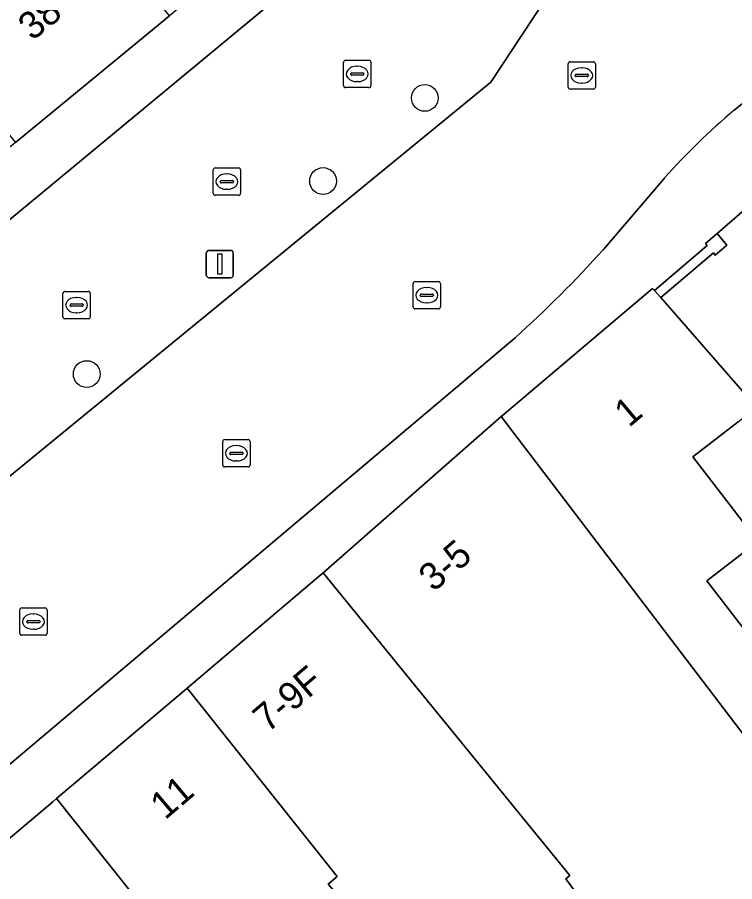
# Model space of a CAD drawing. Extents: x 161087 to 161926, y 382572 to 383873.
# Drawn here: x 161336.63 to 161362.85, y 383067.62 to 383099.2 of the extents above; entities that cross this region are included whole.
import ezdxf

# ---------------------------------------------------------------- set-up
doc = ezdxf.new("R2010")
doc.units = 0
for name, color, linetype in [('IMGEO_Boom', 7, 'Continuous'), ('IMGEO_Erf', 7, 'Continuous'), ('IMGEO_Kolk', 7, 'Continuous'), ('IMGEO_Lichtmast', 7, 'Continuous'), ('IMGEO_Muur', 7, 'Continuous'), ('IMGEO_Pand', 7, 'Continuous'), ('IMGEO_Pand_nummerreeks', 7, 'Continuous'), ('IMGEO_Rijbaan_lokaal_open', 7, 'Continuous'), ('IMGEO_Voetgangersgebied_open', 7, 'Continuous'), ('IMGEO_Voetpad_open', 7, 'Continuous')]:
    doc.layers.add(name, color=color, linetype=linetype)

msp = doc.modelspace()

# ---------------------------------------------------------------- linework, layer by layer
at = {"layer": 'IMGEO_Boom'}
for centre in [(161351.524, 383096.259), (161347.806, 383093.222), (161339.171, 383086.168)]:
    msp.add_circle(centre, 0.489, dxfattribs=at)
at = {"layer": 'IMGEO_Erf'}
for points in [[(161363.584, 383092.504), (161362.202, 383091.306), (161362.565, 383090.88), (161362.138, 383090.517), (161362.067, 383090.601), (161360.142, 383088.963), (161363.648, 383084.959)], [(161362.972, 383084.424), (161361.312, 383083.146), (161362.666, 383081.388), (161363.693, 383080.054), (161361.831, 383078.62), (161365.218, 383074.222)]]:
    msp.add_lwpolyline(points, dxfattribs=at)
at = {"layer": 'IMGEO_Kolk'}
for p, q in [((161348.631, 383097.633), (161349.483, 383097.633)), ((161348.556, 383096.707), (161348.556, 383097.559)), ((161349.044, 383097.413), (161349.069, 383097.413)), ((161349.557, 383097.559), (161349.557, 383096.707)), ((161356.758, 383096.653), (161356.758, 383097.505)), ((161356.833, 383097.579), (161357.685, 383097.579)), ((161357.246, 383097.359), (161357.271, 383097.359)), ((161357.759, 383097.505), (161357.759, 383096.653)), ((161348.815, 383097.127), (161348.815, 383097.139)), ((161349.253, 383097.09), (161348.855, 383097.09)), ((161348.858, 383097.176), (161349.256, 383097.176)), ((161349.299, 383097.139), (161349.299, 383097.127)), ((161357.017, 383097.073), (161357.017, 383097.085)), ((161357.455, 383097.036), (161357.057, 383097.036)), ((161357.06, 383097.122), (161357.458, 383097.122)), ((161357.501, 383097.085), (161357.501, 383097.073)), ((161349.067, 383096.853), (161349.042, 383096.853)), ((161357.269, 383096.799), (161357.244, 383096.799)), ((161349.483, 383096.633), (161348.631, 383096.633)), ((161357.685, 383096.579), (161356.833, 383096.579)), ((161343.792, 383092.773), (161343.792, 383093.625)), ((161343.867, 383093.699), (161344.719, 383093.699)), ((161344.793, 383093.625), (161344.793, 383092.773)), ((161344.051, 383093.193), (161344.051, 383093.205)), ((161344.094, 383093.242), (161344.492, 383093.242)), ((161344.28, 383093.479), (161344.305, 383093.479)), ((161344.535, 383093.205), (161344.535, 383093.193)), ((161344.489, 383093.156), (161344.091, 383093.156)), ((161344.303, 383092.919), (161344.278, 383092.919)), ((161344.719, 383092.699), (161343.867, 383092.699)), ((161351.096, 383088.623), (161351.096, 383089.475)), ((161351.171, 383089.549), (161352.023, 383089.549)), ((161352.097, 383089.475), (161352.097, 383088.623)), ((161338.301, 383088.263), (161338.301, 383089.115)), ((161338.376, 383089.189), (161339.228, 383089.189)), ((161339.302, 383089.115), (161339.302, 383088.263)), ((161351.584, 383089.329), (161351.609, 383089.329)), ((161338.789, 383088.969), (161338.814, 383088.969)), ((161351.355, 383089.043), (161351.355, 383089.055)), ((161351.793, 383089.006), (161351.395, 383089.006)), ((161351.398, 383089.092), (161351.796, 383089.092)), ((161351.839, 383089.055), (161351.839, 383089.043)), ((161338.56, 383088.683), (161338.56, 383088.695)), ((161338.998, 383088.646), (161338.6, 383088.646)), ((161338.603, 383088.732), (161339.001, 383088.732)), ((161339.044, 383088.695), (161339.044, 383088.683)), ((161352.023, 383088.549), (161351.171, 383088.549)), ((161351.607, 383088.769), (161351.582, 383088.769)), ((161339.228, 383088.189), (161338.376, 383088.189)), ((161338.812, 383088.409), (161338.787, 383088.409)), ((161344.214, 383083.774), (161345.066, 383083.774)), ((161344.139, 383082.848), (161344.139, 383083.7)), ((161344.627, 383083.554), (161344.652, 383083.554)), ((161345.14, 383083.7), (161345.14, 383082.848)), ((161344.398, 383083.268), (161344.398, 383083.28)), ((161344.836, 383083.231), (161344.438, 383083.231)), ((161344.441, 383083.317), (161344.839, 383083.317)), ((161344.882, 383083.28), (161344.882, 383083.268)), ((161344.65, 383082.994), (161344.625, 383082.994)), ((161345.066, 383082.774), (161344.214, 383082.774)), ((161336.722, 383076.698), (161336.722, 383077.55)), ((161336.797, 383077.624), (161337.649, 383077.624)), ((161337.723, 383077.55), (161337.723, 383076.698)), ((161336.981, 383077.118), (161336.981, 383077.13)), ((161337.024, 383077.167), (161337.422, 383077.167)), ((161337.21, 383077.404), (161337.235, 383077.404)), ((161337.465, 383077.13), (161337.465, 383077.118)), ((161337.419, 383077.081), (161337.021, 383077.081)), ((161337.233, 383076.844), (161337.208, 383076.844)), ((161337.649, 383076.624), (161336.797, 383076.624))]:
    msp.add_line(p, q, dxfattribs=at)
for points in [[(161348.631, 383097.633), (161349.483, 383097.633)], [(161348.556, 383096.707), (161348.556, 383097.559)], [(161349.557, 383097.559), (161349.557, 383096.707)], [(161356.758, 383096.653), (161356.758, 383097.505)], [(161356.833, 383097.579), (161357.685, 383097.579)], [(161357.759, 383097.505), (161357.759, 383096.653)], [(161349.483, 383096.633), (161348.631, 383096.633)], [(161357.685, 383096.579), (161356.833, 383096.579)], [(161343.792, 383092.773), (161343.792, 383093.625)], [(161343.867, 383093.699), (161344.719, 383093.699)], [(161344.793, 383093.625), (161344.793, 383092.773)], [(161344.719, 383092.699), (161343.867, 383092.699)], [(161351.096, 383088.623), (161351.096, 383089.475)], [(161351.171, 383089.549), (161352.023, 383089.549)], [(161352.097, 383089.475), (161352.097, 383088.623)], [(161338.301, 383088.263), (161338.301, 383089.115)], [(161338.376, 383089.189), (161339.228, 383089.189)], [(161339.302, 383089.115), (161339.302, 383088.263)], [(161352.023, 383088.549), (161351.171, 383088.549)], [(161339.228, 383088.189), (161338.376, 383088.189)], [(161344.214, 383083.774), (161345.066, 383083.774)], [(161344.139, 383082.848), (161344.139, 383083.7)], [(161345.14, 383083.7), (161345.14, 383082.848)], [(161345.066, 383082.774), (161344.214, 383082.774)], [(161336.722, 383076.698), (161336.722, 383077.55)], [(161336.797, 383077.624), (161337.649, 383077.624)], [(161337.723, 383077.55), (161337.723, 383076.698)], [(161337.649, 383076.624), (161336.797, 383076.624)]]:
    msp.add_lwpolyline(points, dxfattribs=at)
for centre, radius, start, end in [((161348.633, 383097.557), 0.0765, 91.552, 178.448), ((161348.633, 383097.557), 0.0765, 91.552, 178.448), ((161349.481, 383097.557), 0.0765, 1.552, 88.448), ((161349.481, 383097.557), 0.0765, 1.552, 88.448), ((161356.835, 383097.503), 0.0765, 91.552, 178.448), ((161356.835, 383097.503), 0.0765, 91.552, 178.448), ((161357.683, 383097.503), 0.0765, 1.552, 88.448), ((161357.683, 383097.503), 0.0765, 1.552, 88.448), ((161348.855, 383097.136), 0.0403, 85.8775, 175.7526), ((161348.852, 383097.126), 0.0366, 178.938, 274.7102), ((161349.256, 383097.133), 0.043, 264.8664, 352.4533), ((161349.26, 383097.138), 0.0386, 1.7309, 96.639), ((161357.057, 383097.082), 0.0403, 85.8775, 175.7526), ((161357.054, 383097.072), 0.0366, 178.938, 274.7102), ((161357.458, 383097.079), 0.043, 264.8664, 352.4533), ((161357.462, 383097.084), 0.0386, 1.7309, 96.639), ((161348.633, 383096.709), 0.0765, 181.552, 268.448), ((161348.633, 383096.709), 0.0765, 181.552, 268.448), ((161349.481, 383096.709), 0.0765, 271.552, 358.448), ((161349.481, 383096.709), 0.0765, 271.552, 358.448), ((161356.835, 383096.655), 0.0765, 181.552, 268.448), ((161356.835, 383096.655), 0.0765, 181.552, 268.448), ((161357.683, 383096.655), 0.0765, 271.552, 358.448), ((161357.683, 383096.655), 0.0765, 271.552, 358.448), ((161343.869, 383093.623), 0.0765, 91.552, 178.448), ((161343.869, 383093.623), 0.0765, 91.552, 178.448), ((161344.717, 383093.623), 0.0765, 1.552, 88.448), ((161344.717, 383093.623), 0.0765, 1.552, 88.448), ((161344.091, 383093.202), 0.0403, 85.8775, 175.7526), ((161344.496, 383093.204), 0.0386, 1.7309, 96.639), ((161344.088, 383093.192), 0.0366, 178.938, 274.7102), ((161344.492, 383093.199), 0.043, 264.8664, 352.4533), ((161343.869, 383092.775), 0.0765, 181.552, 268.448), ((161343.869, 383092.775), 0.0765, 181.552, 268.448), ((161344.717, 383092.775), 0.0765, 271.552, 358.448), ((161344.717, 383092.775), 0.0765, 271.552, 358.448), ((161351.173, 383089.473), 0.0765, 91.552, 178.448), ((161351.173, 383089.473), 0.0765, 91.552, 178.448), ((161352.021, 383089.473), 0.0765, 1.552, 88.448), ((161352.021, 383089.473), 0.0765, 1.552, 88.448), ((161338.378, 383089.113), 0.0765, 91.552, 178.448), ((161338.378, 383089.113), 0.0765, 91.552, 178.448), ((161339.226, 383089.113), 0.0765, 1.552, 88.448), ((161339.226, 383089.113), 0.0765, 1.552, 88.448), ((161351.395, 383089.052), 0.0403, 85.8775, 175.7526), ((161351.392, 383089.042), 0.0366, 178.938, 274.7102), ((161351.796, 383089.049), 0.043, 264.8664, 352.4533), ((161351.8, 383089.054), 0.0386, 1.7309, 96.639), ((161338.6, 383088.692), 0.0403, 85.8775, 175.7526), ((161338.597, 383088.682), 0.0366, 178.938, 274.7102), ((161339.001, 383088.689), 0.043, 264.8664, 352.4533), ((161339.005, 383088.694), 0.0386, 1.7309, 96.639), ((161351.173, 383088.625), 0.0765, 181.552, 268.448), ((161351.173, 383088.625), 0.0765, 181.552, 268.448), ((161352.021, 383088.625), 0.0765, 271.552, 358.448), ((161352.021, 383088.625), 0.0765, 271.552, 358.448), ((161338.378, 383088.265), 0.0765, 181.552, 268.448), ((161338.378, 383088.265), 0.0765, 181.552, 268.448), ((161339.226, 383088.265), 0.0765, 271.552, 358.448), ((161339.226, 383088.265), 0.0765, 271.552, 358.448), ((161344.216, 383083.698), 0.0765, 91.552, 178.448), ((161344.216, 383083.698), 0.0765, 91.552, 178.448), ((161345.064, 383083.698), 0.0765, 1.552, 88.448), ((161345.064, 383083.698), 0.0765, 1.552, 88.448), ((161344.438, 383083.277), 0.0403, 85.8775, 175.7526), ((161344.435, 383083.267), 0.0366, 178.938, 274.7102), ((161344.839, 383083.274), 0.043, 264.8664, 352.4533), ((161344.843, 383083.279), 0.0386, 1.7309, 96.639), ((161344.216, 383082.85), 0.0765, 181.552, 268.448), ((161344.216, 383082.85), 0.0765, 181.552, 268.448), ((161345.064, 383082.85), 0.0765, 271.552, 358.448), ((161345.064, 383082.85), 0.0765, 271.552, 358.448), ((161336.799, 383077.548), 0.0765, 91.552, 178.448), ((161336.799, 383077.548), 0.0765, 91.552, 178.448), ((161337.647, 383077.548), 0.0765, 1.552, 88.448), ((161337.647, 383077.548), 0.0765, 1.552, 88.448), ((161337.021, 383077.127), 0.0403, 85.8775, 175.7526), ((161337.018, 383077.117), 0.0366, 178.938, 274.7102), ((161337.422, 383077.124), 0.043, 264.8664, 352.4533), ((161337.426, 383077.129), 0.0386, 1.7309, 96.639), ((161336.799, 383076.7), 0.0765, 181.552, 268.448), ((161336.799, 383076.7), 0.0765, 181.552, 268.448), ((161337.647, 383076.7), 0.0765, 271.552, 358.448), ((161337.647, 383076.7), 0.0765, 271.552, 358.448)]:
    msp.add_arc(centre, radius, start, end, dxfattribs=at)
for centre, major_axis, ratio, start_param, end_param in [((161349.043, 383097.133), (-0.387, 0.002), 0.722429, 4.712389, 7.853982), ((161349.068, 383097.133), (-0.39, 0.002), 0.717154, 1.570796, 4.712389), ((161357.245, 383097.079), (-0.387, 0.002), 0.722429, 4.712389, 7.853982), ((161357.27, 383097.079), (-0.39, 0.002), 0.717154, 1.570796, 4.712389), ((161344.279, 383093.199), (-0.387, 0.002), 0.722429, 4.712389, 7.853982), ((161344.304, 383093.199), (-0.39, 0.002), 0.717154, 1.570796, 4.712389), ((161351.583, 383089.049), (-0.387, 0.002), 0.722429, 4.712389, 7.853982), ((161351.608, 383089.049), (-0.39, 0.002), 0.717154, 1.570796, 4.712389), ((161338.788, 383088.689), (-0.387, 0.002), 0.722429, 4.712389, 7.853982), ((161338.813, 383088.689), (-0.39, 0.002), 0.717154, 1.570796, 4.712389), ((161344.626, 383083.274), (-0.387, 0.002), 0.722429, 4.712389, 7.853982), ((161344.651, 383083.274), (-0.39, 0.002), 0.717154, 1.570796, 4.712389), ((161337.209, 383077.124), (-0.387, 0.002), 0.722429, 4.712389, 7.853982), ((161337.234, 383077.124), (-0.39, 0.002), 0.717154, 1.570796, 4.712389)]:
    msp.add_ellipse(centre, major_axis=major_axis, ratio=ratio, start_param=start_param, end_param=end_param, dxfattribs=at)
at = {"layer": 'IMGEO_Lichtmast'}
for p, q in [((161343.637, 383090.688), (161344.427, 383090.688)), ((161344.427, 383090.688), (161343.637, 383090.688)), ((161343.537, 383089.788), (161343.537, 383090.588)), ((161343.537, 383090.588), (161343.537, 383089.788)), ((161344.527, 383090.588), (161344.527, 383089.788)), ((161344.527, 383089.788), (161344.527, 383090.588)), ((161344.427, 383089.688), (161343.637, 383089.688)), ((161343.637, 383089.688), (161344.427, 383089.688))]:
    msp.add_line(p, q, dxfattribs=at)
msp.add_lwpolyline([(161343.957, 383090.563), (161344.107, 383090.563), (161344.107, 383089.813), (161343.957, 383089.813), (161343.957, 383090.563)], dxfattribs=at)
for centre, start, end in [((161343.637, 383090.588), 90, 180), ((161343.637, 383090.588), 90, 180), ((161344.427, 383090.588), 0, 90), ((161344.427, 383090.588), 360, 90), ((161343.637, 383089.788), 180, 270), ((161343.637, 383089.788), 180, 270), ((161344.427, 383089.788), 270, 0), ((161344.427, 383089.788), 270, 0)]:
    msp.add_arc(centre, 0.1, start, end, dxfattribs=at)
at = {"layer": 'IMGEO_Muur'}
msp.add_lwpolyline([(161361.775, 383090.944), (161361.847, 383090.86), (161359.918, 383089.219), (161360.142, 383088.963), (161362.067, 383090.601), (161362.138, 383090.517), (161362.565, 383090.88), (161362.202, 383091.306)], close=True, dxfattribs=at)
at = {"layer": 'IMGEO_Pand'}
for points in [[(161342.197, 383099.261), (161328.949, 383115.484), (161323.371, 383110.78), (161336.573, 383094.624)], [(161364.102, 383073.291), (161365.218, 383074.222), (161361.831, 383078.62), (161363.693, 383080.054), (161362.666, 383081.388), (161361.312, 383083.146), (161362.972, 383084.424), (161363.648, 383084.959), (161360.142, 383088.963), (161359.918, 383089.219), (161359.849, 383089.298), (161354.364, 383084.66), (161354.318, 383084.62), (161363.242, 383072.901), (161363.972, 383073.474)], [(161356.973, 383067.319), (161365.873, 383055.306), (161366.508, 383055.762), (161373.165, 383060.545), (161363.982, 383073.191), (161364.102, 383073.291), (161363.972, 383073.474), (161363.242, 383072.901), (161354.318, 383084.62), (161347.804, 383078.905), (161356.825, 383067.846), (161356.673, 383067.725)], [(161342.835, 383074.693), (161348.322, 383067.806), (161347.987, 383067.529), (161352.289, 383062.57), (161352.053, 383062.349), (161359.093, 383053.183), (161363.477, 383047.313), (161365.909, 383044.313), (161369.037, 383046.737), (161357.97, 383061.02), (161358.407, 383061.359), (161355.077, 383065.731), (161356.973, 383067.319), (161356.673, 383067.725), (161356.825, 383067.846), (161347.804, 383078.905), (161347.663, 383078.781)], [(161360.44, 383040.09), (161360.786, 383040.357), (161365.785, 383044.217), (161365.909, 383044.313), (161363.477, 383047.313), (161359.093, 383053.183), (161352.053, 383062.349), (161352.289, 383062.57), (161347.987, 383067.529), (161348.322, 383067.806), (161342.835, 383074.693), (161342.739, 383074.613), (161338.071, 383070.66), (161345.668, 383061.123), (161348.807, 383056.868), (161353.875, 383050.364), (161352.97, 383049.659), (161357.01, 383044.483)], [(161343.591, 383052.648), (161348.807, 383056.868), (161345.668, 383061.123), (161338.071, 383070.66), (161337.93, 383070.541), (161332.485, 383065.961), (161338.407, 383058.427), (161340.56, 383056.66), (161342.833, 383053.65)]]:
    msp.add_lwpolyline(points, close=True, dxfattribs=at)
at = {"layer": 'IMGEO_Rijbaan_lokaal_open'}
for points in [[(161362.829, 383095.814), (161364.77, 383097.35), (161362.866, 383099.876), (161359.598, 383104.154), (161357.76, 383102.637), (161353.934, 383096.833), (161331.379, 383078.376), (161324.754, 383073.591), (161319.89, 383069.645), (161317.769, 383067.924), (161324.746, 383059.32), (161325.561, 383058.315)], [(161358.051, 383090.722), (161360.276, 383093.328)], [(161325.261, 383062.484), (161325.595, 383062.843), (161354.821, 383087.495)]]:
    msp.add_lwpolyline(points, dxfattribs=at)
for centre, radius, start, end in [((161379.428, 383076.213), 25.685, 130.2606, 138.2159), ((161326.347, 383119.226), 42.634, 311.9039, 318.0429)]:
    msp.add_arc(centre, radius, start, end, dxfattribs=at)
at = {"layer": 'IMGEO_Voetgangersgebied_open'}
for points in [[(161353.934, 383096.833), (161357.76, 383102.637), (161355.325, 383105.517), (161357.325, 383107.176), (161353.567, 383112.777), (161350.565, 383110.309), (161346.896, 383114.722), (161346.807, 383114.65), (161342.789, 383111.42), (161342.668, 383111.323), (161349.672, 383102.844), (161315.817, 383074.812), (161319.89, 383069.645), (161324.754, 383073.591), (161331.379, 383078.376)], [(161349.672, 383102.844), (161342.668, 383111.323), (161342.3, 383111.027), (161348.002, 383104.048), (161342.197, 383099.261), (161336.573, 383094.624), (161325.68, 383085.643), (161314.528, 383076.448), (161313.477, 383075.634), (161314.803, 383073.972), (161315.817, 383074.812)]]:
    msp.add_lwpolyline(points, close=True, dxfattribs=at)
at = {"layer": 'IMGEO_Voetpad_open'}
for points in [[(161354.318, 383084.62), (161354.364, 383084.66), (161359.849, 383089.298), (161359.918, 383089.219), (161361.847, 383090.86), (161361.775, 383090.944), (161362.202, 383091.306), (161363.584, 383092.504), (161364.011, 383092.86), (161364.081, 383092.776), (161366.403, 383094.737), (161366.332, 383094.821), (161366.565, 383095.02), (161364.77, 383097.35), (161362.829, 383095.814)], [(161360.276, 383093.328), (161358.051, 383090.722)], [(161354.821, 383087.495), (161325.595, 383062.843), (161325.261, 383062.484), (161326.89, 383060.523)], [(161327.199, 383061.585), (161328.085, 383062.31), (161328.256, 383062.101), (161330.489, 383063.928), (161330.317, 383064.136), (161332.485, 383065.961), (161337.93, 383070.541), (161338.071, 383070.66), (161342.739, 383074.613), (161342.835, 383074.693), (161347.663, 383078.781), (161347.804, 383078.905), (161354.318, 383084.62)]]:
    msp.add_lwpolyline(points, dxfattribs=at)
for centre, radius, start, end in [((161379.428, 383076.213), 25.685, 130.2606, 138.2159), ((161326.347, 383119.226), 42.634, 311.9039, 318.0429)]:
    msp.add_arc(centre, radius, start, end, dxfattribs=at)

# ---------------------------------------------------------------- texts
at = {"layer": 'IMGEO_Pand_nummerreeks'}
for s, rotation, p in [('38', 39.3951, (161337.189, 383098.319)), ('1', 40.1366, (161358.983, 383084.195)), ('3-5', 40.3262, (161351.841, 383078.183)), ('7-9F', 40.3262, (161345.784, 383073.041)), ('11', 40.3262, (161342.034, 383069.858))]:
    msp.add_text(s, height=1, rotation=rotation, dxfattribs=at).set_placement(p)

doc.saveas('drawing.dxf')
